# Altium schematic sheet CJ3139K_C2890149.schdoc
size 127 x 101 mm
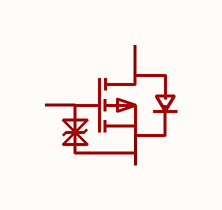
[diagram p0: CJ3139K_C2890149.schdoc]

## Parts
Q?  cj3139k  [SOT-23-3_L2.9-W1.3-P1.90-LS2.4-BR]  (value not drawn)

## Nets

Not connected (* = marked no-connect by the designer): Q? 1(G) 2(S) 3(D)

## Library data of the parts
Q? = cj3139k: 数量:1个P沟道;漏源电压(Vdss):20V;连续漏极电流(Id):660mA;导通电阻(RDS(on)):700mΩ@2.5V;耗散功率(Pd):350mW;阈值电压(Vgs(th)):1.1V;; Manufacturer: CJ(江苏长电/长晶); Symbol: CJ3139K_C2890149; AddInBom: yes; ModelId: c62791f0466c4ae2a892c056b845b0ca; ModelName: SOT-23-3P_L2.9-W1.3-H1.0-LS2.4-P0.95; ModelTransform: 98.425,114.173,0,180,0,0,0.0005,-0.0005,0; Number: 1个P沟道; Drain to Source Voltage: 20V; Current - Continuous Drain(Id): 660mA; Pd - Power Dissipation: 350mW; Gate Threshold Voltage (Vgs(th)): 1.1V; Input Capacitance(Ciss): 170pF; Reverse Transfer Capacitance (Crss@Vds): 15pF; Type: P沟道; Output Capacitance(Coss): 25pF; Vgs: ±12V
